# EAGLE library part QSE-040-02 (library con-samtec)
0,80mm HI-SPEED SOCKET QSE Serie Source: http://www.samtec.com/ftppub/cpdf/QSE-XXX-01-X-D-XX-FOOTPRINT.pdf http://www.samtec.com/ftppub/pdf/QSE.PDF
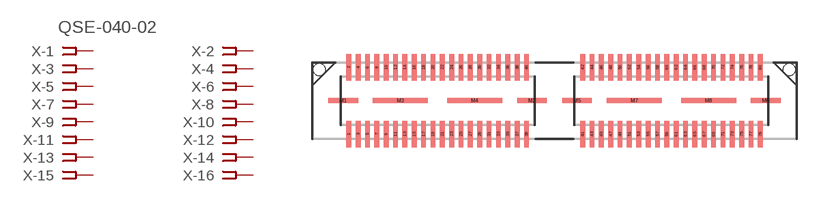
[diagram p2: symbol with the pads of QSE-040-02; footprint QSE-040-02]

Designator prefix X; gates -1=FPINV -2=FPIN -3=FPIN -4=FPIN -5=FPIN -6=FPIN -7=FPIN -8=FPIN -9=FPIN -10=FPIN -11=FPIN -12=FPIN -13=FPIN -14=FPIN -15=FPIN -16=FPIN -17=FPIN -18=FPIN -19=FPIN -20=FPIN -21=FPIN -22=FPIN -23=FPIN -24=FPIN -25=FPIN -26=FPIN -27=FPIN -28=FPIN -29=FPIN -30=FPIN -31=FPIN -32=FPIN -33=FPIN -34=FPIN -35=FPIN -36=FPIN -37=FPIN -38=FPIN -39=FPIN -40=FPIN -41=FPIN -42=FPIN -43=FPIN -44=FPIN -45=FPIN -46=FPIN -47=FPIN -48=FPIN -49=FPIN -50=FPIN -51=FPIN -52=FPIN -53=FPIN -54=FPIN -55=FPIN -56=FPIN -57=FPIN -58=FPIN -59=FPIN -60=FPIN -61=FPIN -62=FPIN -63=FPIN -64=FPIN -65=FPIN -66=FPIN -67=FPIN -68=FPIN -69=FPIN -70=FPIN -71=FPIN -72=FPIN -73=FPIN -74=FPIN -75=FPIN -76=FPIN -77=FPIN -78=FPIN -79=FPIN -80=FPIN

## QSE-040-02 (OC_FARNELL: unknown; OC_NEWARK: unknown)  [QSE-040-02]
1  -1:1  pas
2  -2:1  pas
3  -3:1  pas
4  -4:1  pas
5  -5:1  pas
6  -6:1  pas
7  -7:1  pas
8  -8:1  pas
9  -9:1  pas
10  -10:1  pas
11  -11:1  pas
12  -12:1  pas
13  -13:1  pas
14  -14:1  pas
15  -15:1  pas
16  -16:1  pas
17  -17:1  pas
18  -18:1  pas
19  -19:1  pas
20  -20:1  pas
21  -21:1  pas
22  -22:1  pas
23  -23:1  pas
24  -24:1  pas
25  -25:1  pas
26  -26:1  pas
27  -27:1  pas
28  -28:1  pas
29  -29:1  pas
30  -30:1  pas
31  -31:1  pas
32  -32:1  pas
33  -33:1  pas
34  -34:1  pas
35  -35:1  pas
36  -36:1  pas
37  -37:1  pas
38  -38:1  pas
39  -39:1  pas
40  -40:1  pas
41  -41:1  pas
42  -42:1  pas
43  -43:1  pas
44  -44:1  pas
45  -45:1  pas
46  -46:1  pas
47  -47:1  pas
48  -48:1  pas
49  -49:1  pas
50  -50:1  pas
51  -51:1  pas
52  -52:1  pas
53  -53:1  pas
54  -54:1  pas
55  -55:1  pas
56  -56:1  pas
57  -57:1  pas
58  -58:1  pas
59  -59:1  pas
60  -60:1  pas
61  -61:1  pas
62  -62:1  pas
63  -63:1  pas
64  -64:1  pas
65  -65:1  pas
66  -66:1  pas
67  -67:1  pas
68  -68:1  pas
69  -69:1  pas
70  -70:1  pas
71  -71:1  pas
72  -72:1  pas
73  -73:1  pas
74  -74:1  pas
75  -75:1  pas
76  -76:1  pas
77  -77:1  pas
78  -78:1  pas
79  -79:1  pas
80  -80:1  pas

## Footprint QSE-040-02 (pad centres in mm)
0,80mm HI-SPEED SOCKET QSE Serie Source: http://www.samtec.com/ftppub/cpdf/QSE-XXX-01-X-D-XX-FOOTPRINT.pdf http://www.samtec.com/ftppub/pdf/QSE.PDF
smd 0.41 x 2.27: 1 -17.595,-2.86; 2 -17.595,2.87; 3 -16.795,-2.86; 4 -16.795,2.87; 5 -15.995,-2.86; 6 -15.995,2.87; 7 -15.195,-2.86; 8 -15.195,2.87; 9 -14.395,-2.86; 10 -14.395,2.87; 11 -13.595,-2.86; 12 -13.595,2.87; 13 -12.795,-2.86; 14 -12.795,2.87; 15 -11.995,-2.86; 16 -11.995,2.87; 17 -11.195,-2.86; 18 -11.195,2.87; 19 -10.395,-2.86; 20 -10.395,2.87; 21 -9.595,-2.86; 22 -9.595,2.87; 23 -8.795,-2.86; 24 -8.795,2.87; 25 -7.995,-2.86; 26 -7.995,2.87; 27 -7.195,-2.86; 28 -7.195,2.87; 29 -6.395,-2.86; 30 -6.395,2.87; 31 -5.595,-2.86; 32 -5.595,2.87; 33 -4.795,-2.86; 34 -4.795,2.87; 35 -3.995,-2.86; 36 -3.995,2.87; 37 -3.195,-2.86; 38 -3.195,2.87; 39 -2.395,-2.86; 40 -2.395,2.87; 41 2.405,-2.86; 42 2.405,2.87; 43 3.205,-2.86; 44 3.205,2.87; 45 4.005,-2.86; 46 4.005,2.87; 47 4.805,-2.86; 48 4.805,2.87; 49 5.605,-2.86; 50 5.605,2.87; 51 6.405,-2.86; 52 6.405,2.87; 53 7.205,-2.86; 54 7.205,2.87; 55 8.005,-2.86; 56 8.005,2.87; 57 8.805,-2.86; 58 8.805,2.87; 59 9.605,-2.86; 60 9.605,2.87; 61 10.405,-2.86; 62 10.405,2.87; 63 11.205,-2.86; 64 11.205,2.87; 65 12.005,-2.86; 66 12.005,2.87; 67 12.805,-2.86; 68 12.805,2.87; 69 13.605,-2.86; 70 13.605,2.87; 71 14.405,-2.86; 72 14.405,2.87; 73 15.205,-2.86; 74 15.205,2.87; 75 16.005,-2.86; 76 16.005,2.87; 77 16.805,-2.86; 78 16.805,2.87; 79 17.605,-2.86; 80 17.605,2.87
smd 2.54 x 0.43: M1 -18.065,0; M2 -1.935,0; M5 1.935,0; M6 18.065,0
smd 4.7 x 0.43: M3 -13.175,0; M4 -6.825,0; M7 6.825,0; M8 13.175,0
hole 1.02 at -20.13,2.67
hole 1.02 at 20.065,2.67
